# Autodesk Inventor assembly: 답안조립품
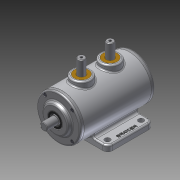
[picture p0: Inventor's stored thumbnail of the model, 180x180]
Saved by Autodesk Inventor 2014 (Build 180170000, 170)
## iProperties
Created: 2014-12
Part Number: 답안조립품
Document SubType Name: Assembly
Designer: Owner
Author: Owner
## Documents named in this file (10)
- C:\Users\Owner\Desktop\441223V1017\답안조립품.iam
- C:\Users\Owner\Desktop\441223V1017\본체.ipt
- C:\Users\Owner\Desktop\441223V1017\M4-소켓머리.ipt
- C:\Users\Owner\Desktop\441223V1017\뒷커버.ipt
- C:\Users\Owner\Desktop\441223V1017\베어링 6203.ipt
- C:\Users\Owner\Desktop\441223V1017\부시.ipt
- C:\Users\Owner\Desktop\441223V1017\슬라이더.ipt
- C:\Users\Owner\Desktop\441223V1017\앞커버.ipt
- C:\Users\Owner\Desktop\441223V1017\오일실.ipt
- C:\Users\Owner\Desktop\441223V1017\축.ipt
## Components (11 placed, 3 different names)
1. 7-베어링 6203:1
2. 8-오일실:1
3. 7-베어링 6203:2
4. 9-M4-소켓머리:1
5. 9-M4-소켓머리:3
6. 9-M4-소켓머리:4
7. 9-M4-소켓머리:5
8. 9-M4-소켓머리:2
9. 9-M4-소켓머리:6
10. 9-M4-소켓머리:7
11. 9-M4-소켓머리:8
